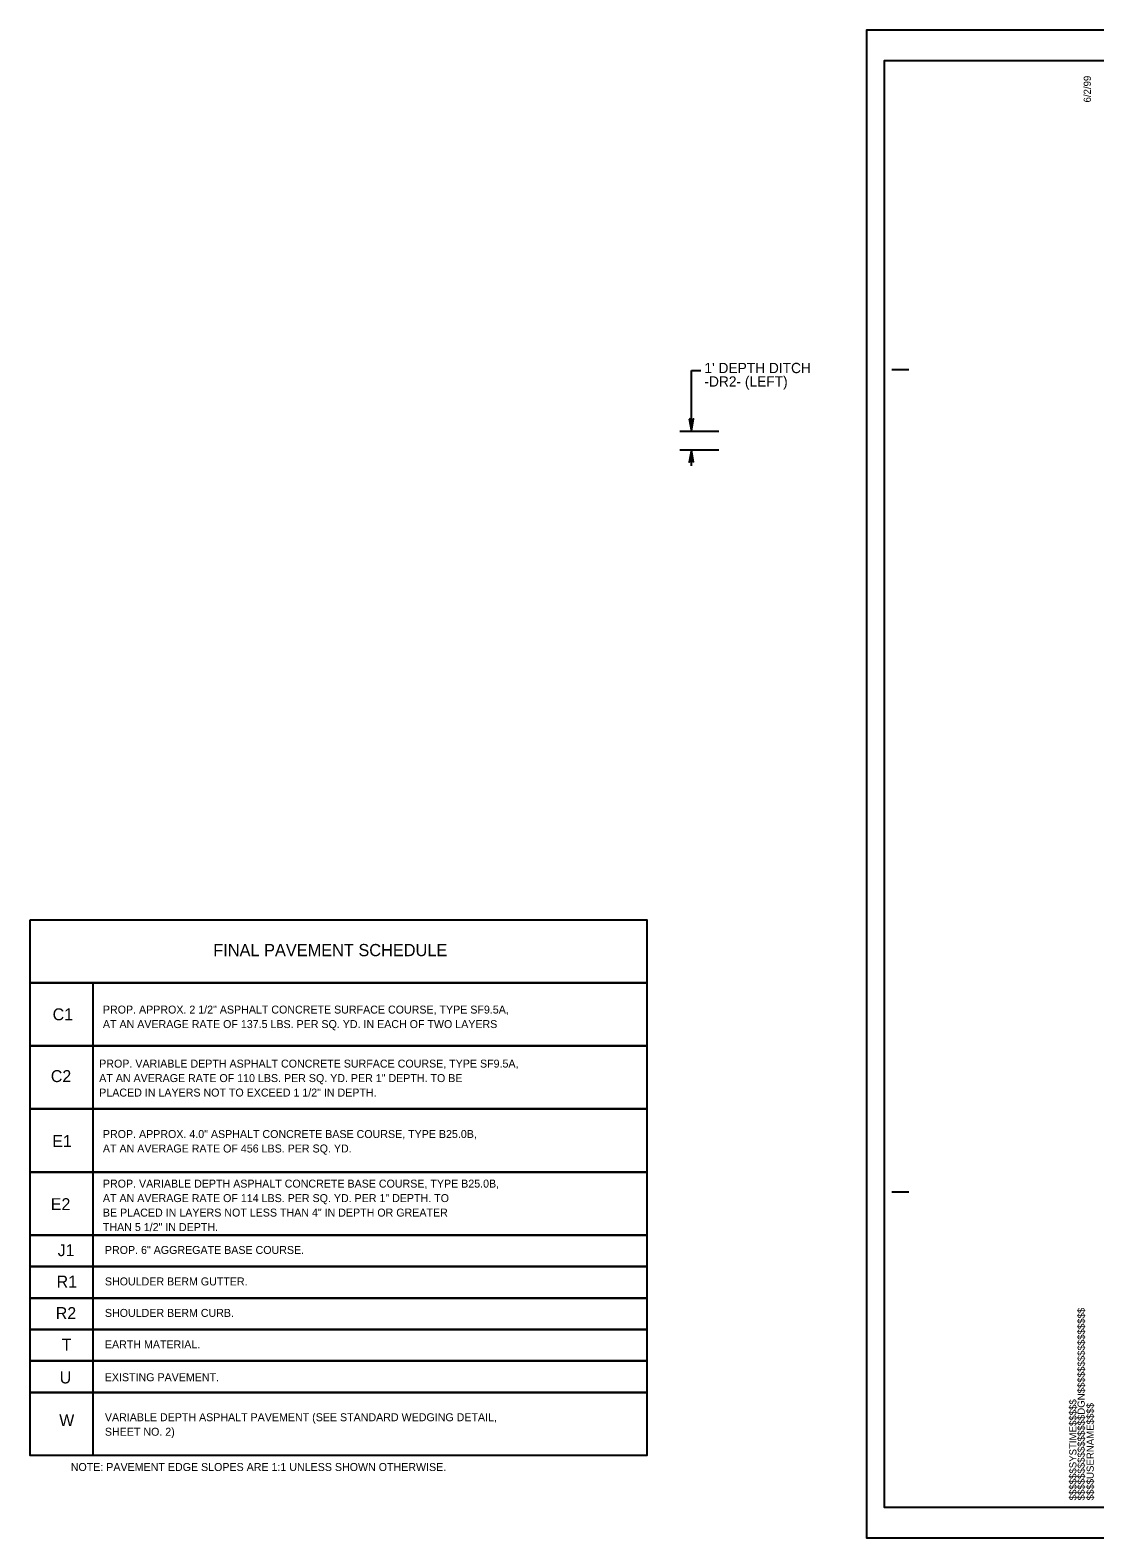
# Model space of a CAD drawing. Extents: x 1542177 to 1542464, y 45134 to 45344.
# Drawn here: x 1542177.2 to 1542239.3, y 45134.4 to 45222.4 of the extents above; entities that cross this region are included whole.
import ezdxf

# ---------------------------------------------------------------- set-up
doc = ezdxf.new("R2010")
doc.units = 0
for name, color, linetype in [('Default', 7, 'Continuous'), ('Sheet Cutting Line CELL', 7, 'Continuous'), ('Sheet Plot Border Inside CELL', 7, 'Continuous'), ('Sheet Plot Border Outside CELL', 7, 'Continuous'), ('Sheet Typical CELL', 7, 'Continuous')]:
    doc.layers.add(name, color=color, linetype=linetype)

msp = doc.modelspace()

# ---------------------------------------------------------------- linework, layer by layer
at = {"layer": 'Default'}
for p, q in [((1542215.791, 45202.593), (1542216.337, 45202.593)), ((1542215.791, 45199.047), (1542215.791, 45202.593)), ((1542215.117, 45199.047), (1542217.385, 45199.047)), ((1542215.117, 45197.957), (1542217.385, 45197.957)), ((1542215.791, 45197.027), (1542215.791, 45197.957)), ((1542180.87, 45142.934), (1542180.87, 45152.119)), ((1542177.235, 45140.116), (1542177.235, 45140.116))]:
    msp.add_line(p, q, dxfattribs=at)
for points in [[(1542215.667, 45199.767), (1542215.791, 45199.047), (1542215.919, 45199.771), (1542215.791, 45199.679)], [(1542215.915, 45197.237), (1542215.791, 45197.957), (1542215.663, 45197.233), (1542215.791, 45197.325)], [(1542177.188, 45170.528), (1542213.189, 45170.528), (1542213.189, 45166.846), (1542177.188, 45166.846)], [(1542177.188, 45152.119), (1542213.188, 45152.119), (1542213.188, 45150.282), (1542180.87, 45150.282), (1542177.188, 45150.282)], [(1542177.188, 45150.282), (1542213.188, 45150.282), (1542213.188, 45148.445), (1542180.87, 45148.445), (1542177.188, 45148.445)], [(1542177.188, 45148.445), (1542213.188, 45148.445), (1542213.188, 45146.608), (1542180.87, 45146.608), (1542177.188, 45146.608)], [(1542177.188, 45146.608), (1542213.188, 45146.608), (1542213.188, 45144.771), (1542180.87, 45144.771), (1542177.188, 45144.771)], [(1542177.188, 45144.771), (1542213.188, 45144.771), (1542213.188, 45142.934), (1542180.87, 45142.934), (1542177.188, 45142.934)]]:
    msp.add_lwpolyline(points, close=True, dxfattribs=at)
for points in [[(1542180.87, 45163.164), (1542177.188, 45163.164), (1542177.188, 45166.846), (1542213.188, 45166.846), (1542213.188, 45163.164), (1542180.87, 45163.164), (1542180.87, 45166.846)], [(1542180.87, 45159.482), (1542177.188, 45159.482), (1542177.188, 45163.164), (1542213.188, 45163.164), (1542213.188, 45159.482), (1542180.87, 45159.482), (1542180.87, 45163.164)], [(1542180.87, 45155.8), (1542177.188, 45155.8), (1542177.188, 45159.482), (1542213.188, 45159.482), (1542213.188, 45155.8), (1542180.87, 45155.8), (1542180.87, 45159.482)], [(1542180.87, 45152.119), (1542177.188, 45152.119), (1542177.188, 45155.8), (1542213.188, 45155.8), (1542213.188, 45152.119), (1542180.87, 45152.119), (1542180.87, 45155.8)], [(1542180.87, 45139.253), (1542177.188, 45139.253), (1542177.188, 45142.934), (1542213.188, 45142.934), (1542213.188, 45139.253), (1542180.87, 45139.253), (1542180.87, 45142.934)]]:
    msp.add_lwpolyline(points, dxfattribs=at)
at = {"layer": 'Sheet Cutting Line CELL'}
for p, q in [((1542360.727, 45222.448), (1542226.007, 45222.448)), ((1542226.007, 45222.448), (1542226.007, 45134.448)), ((1542226.007, 45134.448), (1542360.727, 45134.448))]:
    msp.add_line(p, q, dxfattribs=at)
at = {"layer": 'Sheet Plot Border Inside CELL'}
msp.add_lwpolyline([(1542360.367, 45220.652), (1542227.047, 45220.652), (1542227.047, 45136.244), (1542360.367, 45136.244)], close=True, dxfattribs=at)
at = {"layer": 'Sheet Plot Border Outside CELL'}
msp.add_lwpolyline([(1542360.727, 45222.448), (1542226.007, 45222.448), (1542226.007, 45134.448), (1542360.727, 45134.448)], close=True, dxfattribs=at)
at = {"layer": 'Sheet Typical CELL'}
for p, q in [((1542227.487, 45202.648), (1542228.487, 45202.648)), ((1542227.487, 45154.648), (1542228.487, 45154.648))]:
    msp.add_line(p, q, dxfattribs=at)

# ---------------------------------------------------------------- texts
at = {"layer": 'Default'}
for s, height, p in [("1' DEPTH DITCH", 0.6, (1542216.552, 45202.43)), ('-DR2- (LEFT)', 0.6, (1542216.552, 45201.643)), ('FINAL PAVEMENT SCHEDULE', 0.7125, (1542187.88, 45168.399)), ('C1', 0.6982, (1542178.501, 45164.656)), ('PROP. APPROX. 2 1/2" ASPHALT CONCRETE SURFACE COURSE, TYPE SF9.5A,', 0.46526, (1542181.435, 45165.049)), ('AT AN AVERAGE RATE OF 137.5 LBS. PER SQ. YD. IN EACH OF TWO LAYERS', 0.46526, (1542181.435, 45164.203)), ('C2', 0.6982, (1542178.394, 45161.049)), ('PROP. VARIABLE DEPTH ASPHALT CONCRETE SURFACE COURSE, TYPE SF9.5A,', 0.46526, (1542181.22, 45161.896)), ('AT AN AVERAGE RATE OF 110 LBS. PER SQ. YD. PER 1" DEPTH. TO BE', 0.46526, (1542181.22, 45161.051)), ('PLACED IN LAYERS NOT TO EXCEED 1 1/2" IN DEPTH.', 0.46526, (1542181.22, 45160.206)), ('PROP. APPROX. 4.0" ASPHALT CONCRETE BASE COURSE, TYPE B25.0B,', 0.46526, (1542181.435, 45157.786)), ('E1', 0.6982, (1542178.477, 45157.258)), ('AT AN AVERAGE RATE OF 456 LBS. PER SQ. YD.', 0.46526, (1542181.435, 45156.941)), ('PROP. VARIABLE DEPTH ASPHALT CONCRETE BASE COURSE, TYPE B25.0B,', 0.46526, (1542181.435, 45154.891)), ('E2', 0.6982, (1542178.394, 45153.576)), ('AT AN AVERAGE RATE OF 114 LBS. PER SQ. YD. PER 1" DEPTH. TO', 0.46526, (1542181.435, 45154.046)), ('THAN 5 1/2" IN DEPTH.', 0.46526, (1542181.435, 45152.355)), ('BE PLACED IN LAYERS NOT LESS THAN 4" IN DEPTH OR GREATER', 0.46526, (1542181.435, 45153.2)), ('J1', 0.6982, (1542178.795, 45150.891)), ('PROP. 6" AGGREGATE BASE COURSE.', 0.46526, (1542181.552, 45151.019)), ('R1', 0.6982, (1542178.732, 45149.054)), ('SHOULDER BERM GUTTER.', 0.46526, (1542181.552, 45149.182)), ('R2', 0.6982, (1542178.682, 45147.217)), ('SHOULDER BERM CURB.', 0.46526, (1542181.552, 45147.345)), ('T', 0.698, (1542179.031, 45145.38)), ('EARTH MATERIAL.', 0.46526, (1542181.552, 45145.508)), ('U', 0.698, (1542178.913, 45143.461)), ('EXISTING PAVEMENT.', 0.46526, (1542181.544, 45143.59)), ('W', 0.698, (1542178.884, 45140.967)), ('VARIABLE DEPTH ASPHALT PAVEMENT (SEE STANDARD WEDGING DETAIL,', 0.46526, (1542181.551, 45141.255)), ('SHEET NO. 2)', 0.46526, (1542181.551, 45140.409)), ('NOTE: PAVEMENT EDGE SLOPES ARE 1:1 UNLESS SHOWN OTHERWISE.', 0.46526, (1542179.559, 45138.35))]:
    msp.add_text(s, height=height, dxfattribs=at).set_placement(p)
at = {"layer": 'Sheet Typical CELL'}
for s, p in [('6/2/99', (1542239.115, 45218.228)), ('$$$$$$$$$$$$$$$$DGN$$$$$$$$$$$$$$$$', (1542238.755, 45136.637)), ('$$$$$$SYSTIME$$$$$', (1542238.271, 45136.637)), ('$$$$USERNAME$$$$', (1542239.281, 45136.638))]:
    msp.add_text(s, height=0.42, rotation=90, dxfattribs=at).set_placement(p)

doc.saveas('drawing.dxf')
